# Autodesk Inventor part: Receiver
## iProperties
Created: 2010-02
Part Number: Receiver
Document SubType Name: Modeling
Designer: Администратор
Density: 7.84 g/cm^3
Mass: 266.187 g
Surface Area: 338.386 cm^2
Volume: 33.9525 cm^3
Material: Сталь высокопрочная низколегированная
Author: Администратор
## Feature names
1. Выдавливание1 [Extrusion]
2. Выдавливание2 [Extrusion]
3. Зеркальное отражение1 [Mirror]
4. Выдавливание3 [Extrusion]
5. Зеркальное отражение2 [Mirror]
6. Выдавливание4 [Extrusion]
7. НаклГрань1
8. НаклГрань2
9. НаклГрань3
10. Выдавливание5 [Extrusion]
11. НаклГрань4
12. НаклГрань5
13. НаклГрань6
14. Выдавливание6 [Extrusion]
15. Выдавливание7 [Extrusion]
16. Сопряжение2 [Fillet]
17. Выдавливание8 [Extrusion]
18. Сопряжение3 [Fillet]
19. Выдавливание9 [Extrusion]
20. НаклГрань7
21. НаклГрань8
22. Сопряжение4 [Fillet]
23. Выдавливание10 [Extrusion]
24. Выдавливание11 [Extrusion]
25. Выдавливание12 [Extrusion]
26. Выдавливание13 [Extrusion]
27. Выдавливание14 [Extrusion]
28. Выдавливание19 [Extrusion]
29. Вращение1 [Revolution]
30. Зеркальное отражение9 [Mirror]
31. Выдавливание20 [Extrusion]
32. Выдавливание21 [Extrusion]
33. Сопряжение7 [Fillet]
34. Сопряжение8 [Fillet]
35. Выдавливание22 [Extrusion]
36. Фаска1 [Chamfer]
37. Зеркальное отражение10 [Mirror]
38. Фаска2 [Chamfer]
39. Сдвиг4
40. Зеркальное отражение11 [Mirror]
41. Выдавливание23 [Extrusion]
42. Вращение2 [Revolution]
43. Сопряжение9 [Fillet]
44. Зеркальное отражение12 [Mirror]
45. Сопряжение10 [Fillet]
46. Выдавливание24 [Extrusion]
47. Сопряжение11 [Fillet]
48. Выдавливание25 [Extrusion]
49. Выдавливание26 [Extrusion]
50. Сопряжение12 [Fillet]
51. Выдавливание27 [Extrusion]
52. Выдавливание28 [Extrusion]
53. Выдавливание29 [Extrusion]
54. Выдавливание30 [Extrusion]
55. Выдавливание31 [Extrusion]
56. Выдавливание32 [Extrusion]
57. Выдавливание33 [Extrusion]
58. НаклГрань9
59. НаклГрань10
60. Выдавливание34 [Extrusion]
61. Выдавливание35 [Extrusion]
62. Выдавливание36 [Extrusion]
63. Выдавливание37 [Extrusion]
64. Выдавливание38 [Extrusion]
65. Выдавливание39 [Extrusion]
66. Выдавливание40 [Extrusion]
67. Выдавливание41 [Extrusion]
68. Выдавливание42 [Extrusion]
69. Выдавливание43 [Extrusion]
70. Вращение3 [Revolution]
71. Выдавливание44 [Extrusion]
72. Выдавливание45 [Extrusion]
73. Выдавливание46 [Extrusion]
74. Вращение4 [Revolution]
75. Сопряжение13 [Fillet]
76. Вращение5 [Revolution]
77. Выдавливание47 [Extrusion]
78. Разделение1
79. Разделение2
80. Разделение3
81. Разделение4
82. Разделение5
83. Выдавливание48 [Extrusion]
84. Выдавливание49 [Extrusion]
85. Разделение6
86. Разделение7
87. Разделение8
88. Разделение9
89. Зеркальное отражение13 [Mirror]
90. Выдавливание50 [Extrusion]
91. Выдавливание51 [Extrusion]
92. Выдавливание52 [Extrusion]
93. Зеркальное отражение14 [Mirror]
94. Выдавливание53 [Extrusion]
95. НаклГрань11
96. Выдавливание54 [Extrusion]
97. Разделение10
98. Зеркальное отражение15 [Mirror]
99. Разделение11
100. Разделение12
101. Зеркальное отражение16 [Mirror]
102. Разделение13
103. Разделение14
104. Выдавливание88 [Extrusion]
105. Выдавливание89 [Extrusion]
106. Зеркальное отражение20 [Mirror]
107. Выдавливание90 [Extrusion]
108. Вращение9 [Revolution]
109. Выдавливание91 [Extrusion]
110. Выдавливание92 [Extrusion]
111. Выдавливание104 [Extrusion]
112. Зеркальное отражение21 [Mirror]
113. Выдавливание95 [Extrusion]
114. Зеркальное отражение22 [Mirror]
115. Выдавливание96 [Extrusion]
116. Сдвиг5
117. Выдавливание97 [Extrusion]
118. Зеркальное отражение23 [Mirror]
119. Выдавливание98 [Extrusion]
120. Зеркальное отражение24 [Mirror]
121. Выдавливание99 [Extrusion]
122. Вращение10 [Revolution]
123. Сопряжение17 [Fillet]
124. Вращение11 [Revolution]
125. Выдавливание102 [Extrusion]
126. Выдавливание103 [Extrusion]
127. Зеркальное отражение25 [Mirror]
128. Выдавливание105 [Extrusion]
129. Выдавливание106 [Extrusion]
